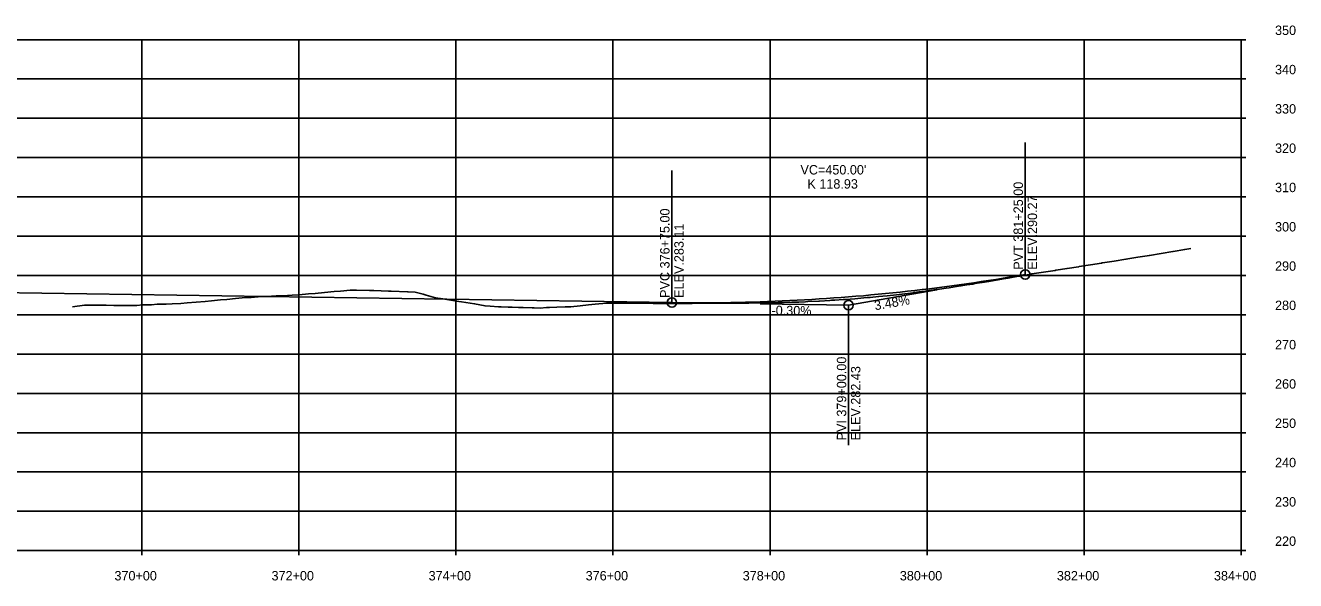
# Model space of a CAD drawing. Extents: x 880555 to 887700, y 1561392 to 1563161.
# Drawn here: x 886082 to 887700, y 1562454 to 1563161 of the extents above; entities that cross this region are included whole.
import ezdxf

# ---------------------------------------------------------------- set-up
doc = ezdxf.new("R2010")
doc.units = 0
for name, color, linetype in [('1', 7, 'Continuous'), ('30', 7, 'Continuous'), ('37', 7, 'Continuous'), ('56', 7, 'Continuous'), ('R_Exist Surface', 7, 'Continuous')]:
    doc.layers.add(name, color=color, linetype=linetype)

msp = doc.modelspace()

# ---------------------------------------------------------------- linework, layer by layer
at = {"layer": '1'}
for p, q in [((887130.6, 1562804.7), (887243.1, 1562824.3)), ((887018.1, 1562806.4), (887130.6, 1562804.7))]:
    msp.add_line(p, q, dxfattribs=at)
at = {"layer": '37'}
for p, q in [((880630.6, 1563142.6), (887630.6, 1563142.6)), ((880630.6, 1563142.6), (887630.6, 1563142.6)), ((886230.6, 1562492.6), (886230.6, 1563142.6)), ((886430.6, 1562492.6), (886430.6, 1563142.6)), ((886630.6, 1562492.6), (886630.6, 1563142.6)), ((886830.6, 1562492.6), (886830.6, 1563142.6)), ((887030.6, 1562492.6), (887030.6, 1563142.6)), ((887230.6, 1562492.6), (887230.6, 1563142.6)), ((887430.6, 1562492.6), (887430.6, 1563142.6)), ((887630.6, 1562492.6), (887630.6, 1563142.6)), ((887636.6, 1563142.6), (887630.6, 1563142.6)), ((887636.6, 1563142.6), (887630.6, 1563142.6)), ((880630.6, 1563092.6), (887630.6, 1563092.6)), ((887636.6, 1563092.6), (887630.6, 1563092.6)), ((880630.6, 1563042.6), (887630.6, 1563042.6)), ((887636.6, 1563042.6), (887630.6, 1563042.6)), ((880630.6, 1562992.6), (887630.6, 1562992.6)), ((887636.6, 1562992.6), (887630.6, 1562992.6)), ((880630.6, 1562942.6), (887630.6, 1562942.6)), ((887636.6, 1562942.6), (887630.6, 1562942.6)), ((880630.6, 1562892.6), (887630.6, 1562892.6)), ((887636.6, 1562892.6), (887630.6, 1562892.6)), ((880630.6, 1562842.6), (887630.6, 1562842.6)), ((887636.6, 1562842.6), (887630.6, 1562842.6)), ((880630.6, 1562792.6), (887630.6, 1562792.6)), ((887636.6, 1562792.6), (887630.6, 1562792.6)), ((880630.6, 1562742.6), (887630.6, 1562742.6)), ((887636.6, 1562742.6), (887630.6, 1562742.6)), ((880630.6, 1562692.6), (887630.6, 1562692.6)), ((887636.6, 1562692.6), (887630.6, 1562692.6)), ((880630.6, 1562642.6), (887630.6, 1562642.6)), ((887636.6, 1562642.6), (887630.6, 1562642.6)), ((880630.6, 1562592.6), (887630.6, 1562592.6)), ((887636.6, 1562592.6), (887630.6, 1562592.6)), ((880630.6, 1562542.6), (887630.6, 1562542.6)), ((887636.6, 1562542.6), (887630.6, 1562542.6)), ((880630.6, 1562492.6), (887630.6, 1562492.6)), ((886230.6, 1562486.6), (886230.6, 1562492.6)), ((886430.6, 1562486.6), (886430.6, 1562492.6)), ((886630.6, 1562486.6), (886630.6, 1562492.6)), ((886830.6, 1562486.6), (886830.6, 1562492.6)), ((887030.6, 1562486.6), (887030.6, 1562492.6)), ((887230.6, 1562486.6), (887230.6, 1562492.6)), ((887430.6, 1562486.6), (887430.6, 1562492.6)), ((887636.6, 1562492.6), (887630.6, 1562492.6)), ((887630.6, 1562486.6), (887630.6, 1562492.6))]:
    msp.add_line(p, q, dxfattribs=at)
at = {"layer": '56'}
for p, q in [((887355.6, 1562843.9), (887355.6, 1563011.9)), ((886905.6, 1562808.1), (886905.6, 1562976.1)), ((885030.6, 1562836.2), (886905.6, 1562808.1)), ((887130.6, 1562804.7), (887130.6, 1562794.7)), ((887130.6, 1562794.7), (887130.6, 1562626.7))]:
    msp.add_line(p, q, dxfattribs=at)
msp.add_lwpolyline([(886905.6, 1562808.1), (886915, 1562808), (886924.4, 1562807.9), (886933.7, 1562807.9), (886943.1, 1562807.8), (886952.5, 1562807.9), (886961.9, 1562807.9), (886971.2, 1562808), (886980.6, 1562808.2), (886990, 1562808.3), (886999.4, 1562808.6), (887008.7, 1562808.8), (887018.1, 1562809.1), (887027.5, 1562809.4), (887036.9, 1562809.8), (887046.2, 1562810.2), (887055.6, 1562810.6), (887065, 1562811.1), (887074.4, 1562811.6), (887083.7, 1562812.1), (887093.1, 1562812.7), (887102.5, 1562813.3), (887111.9, 1562814), (887121.2, 1562814.7), (887140, 1562816.1), (887149.4, 1562816.9), (887158.7, 1562817.8), (887168.1, 1562818.7), (887177.5, 1562819.6), (887186.9, 1562820.5), (887196.2, 1562821.5), (887205.6, 1562822.5), (887215, 1562823.6), (887224.4, 1562824.7), (887233.7, 1562825.8), (887243.1, 1562827), (887252.5, 1562828.2), (887261.9, 1562829.5), (887271.2, 1562830.7), (887280.6, 1562832.1), (887290, 1562833.4), (887299.4, 1562834.8), (887308.7, 1562836.2), (887318.1, 1562837.7), (887327.5, 1562839.2), (887336.9, 1562840.7), (887346.2, 1562842.3), (887355.6, 1562843.9)], dxfattribs=at)
for centre in [(887355.6, 1562843.9), (886905.6, 1562808.1), (887130.6, 1562804.7)]:
    msp.add_circle(centre, 6, dxfattribs=at)
at = {"layer": 'R_Exist Surface'}
msp.add_lwpolyline([(886142.4, 1562802.7), (886157.7, 1562804.8), (886167.5, 1562804.7), (886175.1, 1562804.7), (886185.1, 1562804.7), (886194.9, 1562804.6), (886202.5, 1562804.6), (886212.5, 1562804.5), (886224.2, 1562804.6), (886231.3, 1562805.2), (886242.8, 1562805.2), (886250.2, 1562805.9), (886261.6, 1562806), (886269.3, 1562806.7), (886280.4, 1562806.8), (886288.5, 1562807.6), (886299.9, 1562808.6), (886311.4, 1562809.7), (886319.4, 1562810.4), (886330.7, 1562811.5), (886338.9, 1562812.2), (886350, 1562813.3), (886358.4, 1562814), (886370, 1562814.6), (886378.6, 1562815.4), (886390, 1562815.9), (886401.5, 1562816.5), (886410.4, 1562816.9), (886422, 1562817.5), (886430.8, 1562817.9), (886442.7, 1562819.1), (886451.2, 1562819.6), (886463.3, 1562820.8), (886475.4, 1562822.1), (886483.8, 1562822.5), (886496, 1562823.8), (886504.1, 1562823.8), (886520.4, 1562823.3), (886526.2, 1562823.3), (886544.7, 1562822.6), (886548.1, 1562822.6), (886568.9, 1562821.7), (886569.9, 1562821.7), (886578.8, 1562821.3), (886588.8, 1562818.7), (886592.8, 1562817.7), (886604.4, 1562814.2), (886613.8, 1562812.7), (886631.7, 1562809.8), (886634.3, 1562809.5), (886637.8, 1562808.9), (886654.3, 1562806.6), (886667.7, 1562803.8), (886674.2, 1562803.4), (886684.7, 1562802.9), (886688.3, 1562802.8), (886697, 1562802.4), (886702.3, 1562802.3), (886710.4, 1562802), (886716.3, 1562801.8), (886727.8, 1562801.5), (886730.3, 1562801.4), (886737.8, 1562801.2), (886745.8, 1562801.7), (886749.9, 1562801.9), (886758.9, 1562802.4), (886769.6, 1562802.7), (886772, 1562802.8), (886776.8, 1562802.9), (886788.9, 1562804), (886799.4, 1562805.1), (886807.9, 1562806), (886822.3, 1562807.3), (886833.6, 1562807.3), (886844.1, 1562807.4), (886847.4, 1562807.4), (886854.5, 1562807.4), (886881.9, 1562807.1), (886887, 1562807), (886894.7, 1562806.9), (886906.8, 1562806.9), (886917.6, 1562806.9), (886928.7, 1562806.9), (886931.2, 1562807), (886943.4, 1562807.2), (886948.2, 1562807.2), (886958.4, 1562807.3), (886961.6, 1562807.4), (886973.4, 1562807.5), (886985.1, 1562807.4), (886988.4, 1562807.4), (886993.7, 1562807.4), (887003.4, 1562807.5), (887014.2, 1562807.6), (887018.4, 1562807.6), (887028.4, 1562807.9), (887033.5, 1562808), (887041, 1562808.1), (887048.5, 1562808.3), (887058.5, 1562808.5), (887063.5, 1562808.7), (887067.2, 1562808.8), (887075.6, 1562809.2), (887078.7, 1562809.3), (887092.8, 1562810), (887093.7, 1562810.1), (887106.9, 1562810.9), (887108.7, 1562811), (887108.7, 1562811), (887113.1, 1562811.2), (887123.7, 1562811.9), (887126.5, 1562812.2), (887138.7, 1562813.1), (887138.7, 1562813.1), (887149.9, 1562814.2), (887153.7, 1562814.5), (887158.2, 1562814.8), (887168.7, 1562815.8), (887168.7, 1562815.8), (887179.5, 1562816.8), (887183.7, 1562817.2), (887187.6, 1562817.6), (887198.7, 1562818.9), (887198.7, 1562818.9), (887212.9, 1562820.7), (887213.7, 1562820.8), (887220.2, 1562821.6), (887228.7, 1562822.8), (887228.7, 1562822.8), (887241.8, 1562824.6), (887243.7, 1562824.8), (887243.7, 1562824.8), (887254.9, 1562826.4), (887258.7, 1562826.9), (887258.7, 1562826.9), (887268, 1562828.4), (887273.7, 1562829.3), (887273.7, 1562829.3), (887281.1, 1562830.5), (887288.7, 1562831.7), (887288.7, 1562831.7), (887291.3, 1562832.2), (887303.7, 1562834.2), (887303.7, 1562834.2), (887309.2, 1562835.1), (887318.7, 1562836.7), (887318.7, 1562836.7), (887330.5, 1562838.7), (887333.8, 1562839.3), (887333.8, 1562839.3), (887346.8, 1562841.6), (887348.8, 1562841.9), (887348.8, 1562841.9), (887362.7, 1562844.3), (887363.7, 1562844.5), (887363.7, 1562844.5), (887378.6, 1562846.8), (887378.7, 1562846.8), (887378.7, 1562846.8), (887378.9, 1562846.8), (887393.7, 1562849.1), (887393.7, 1562849.1), (887394.3, 1562849.2), (887408.7, 1562851.5), (887408.7, 1562851.5), (887423.4, 1562853.8), (887423.7, 1562853.8), (887423.7, 1562853.8), (887424, 1562853.9), (887438.7, 1562856.2), (887438.7, 1562856.2), (887452.7, 1562858.4), (887453.6, 1562858.5), (887453.7, 1562858.5), (887453.7, 1562858.5), (887468.6, 1562860.8), (887468.7, 1562860.8), (887468.7, 1562860.8), (887483.6, 1562863.2), (887483.7, 1562863.2), (887483.7, 1562863.2), (887483.8, 1562863.2), (887498.7, 1562865.8), (887498.7, 1562865.7), (887513.6, 1562868.2), (887513.7, 1562868.2), (887513.7, 1562868.2), (887513.8, 1562868.2), (887528.7, 1562870.7), (887528.7, 1562870.7), (887543.6, 1562873.2), (887543.7, 1562873.2), (887543.7, 1562873.2), (887543.7, 1562873.2), (887558.7, 1562875.7), (887558.7, 1562875.7), (887558.7, 1562875.7), (887566.2, 1562876.9)], dxfattribs=at)

# ---------------------------------------------------------------- texts
at = {"layer": '30'}
for s, p in [('350', (887673.6, 1563148.6)), ('350', (887673.6, 1563148.6)), ('340', (887673.6, 1563098.6)), ('330', (887673.6, 1563048.6)), ('320', (887673.6, 1562998.6)), ('310', (887673.6, 1562948.6)), ('300', (887673.6, 1562898.6)), ('290', (887673.6, 1562848.6)), ('280', (887673.6, 1562798.6)), ('270', (887673.6, 1562748.6)), ('260', (887673.6, 1562698.6)), ('250', (887673.6, 1562648.6)), ('240', (887673.6, 1562598.6)), ('230', (887673.6, 1562548.6)), ('220', (887673.6, 1562498.6)), ('370+00', (886195.8, 1562454.6)), ('372+00', (886395.8, 1562454.6)), ('374+00', (886595.8, 1562454.6)), ('376+00', (886795.8, 1562454.6)), ('378+00', (886995.8, 1562454.6)), ('380+00', (887195.8, 1562454.6)), ('382+00', (887395.8, 1562454.6)), ('384+00', (887595.8, 1562454.6))]:
    msp.add_text(s, height=12, dxfattribs=at).set_placement(p)
at = {"layer": '56'}
for s, p in [("VC=450.00'", (887069.3, 1562971.1)), ('K 118.93', (887078.2, 1562953.1))]:
    msp.add_text(s, height=12, dxfattribs=at).set_placement(p)
for s, rotation, p in [('PVT 381+25.00', 90, (887352.6, 1562849.9)), ('ELEV.290.27', 90, (887370.6, 1562849.9)), ('PVC 376+75.00', 90, (886902.6, 1562814.1)), ('ELEV.283.11', 90, (886920.6, 1562814.1)), ('3.48%', 9.8441, (887164.4, 1562798.3)), ('-0.30%', 359.1406, (887032.4, 1562792.3)), ('PVI 379+00.00', 90, (887127.6, 1562632.7)), ('ELEV.282.43', 90, (887145.6, 1562632.7))]:
    msp.add_text(s, height=12, rotation=rotation, dxfattribs=at).set_placement(p)

doc.saveas('drawing.dxf')
